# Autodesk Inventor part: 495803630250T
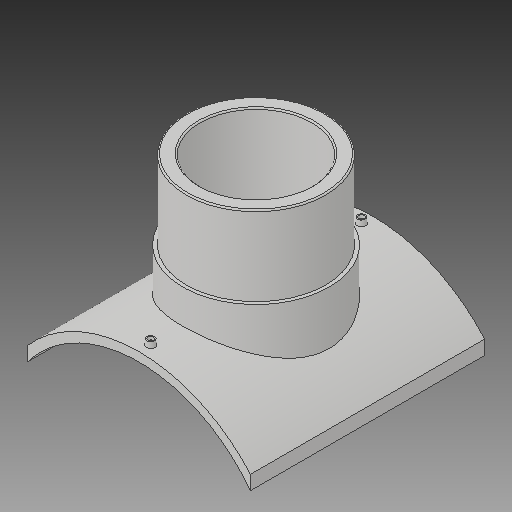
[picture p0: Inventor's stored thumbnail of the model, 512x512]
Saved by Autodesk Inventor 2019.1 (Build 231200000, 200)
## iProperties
Created: 2017-10
Part Number: 495803630250T
Material: Generic
Description: PLASSON BRANCH SADDLE 500x250
Document SubType Name: Modeling
Designer: KIM
Mass: 2754.05 g
Surface Area: 3037.44 cm^2
Volume: 2754.05 cm^3
Density: 1 g/cm^3
Appearance: Default
Author: KIM
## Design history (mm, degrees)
derived "495803.ipt"
feature "Solid1::495803.ipt"
tag "TaggingFeature1"
body "Solid1"
other parameters: "d1" = 16, "d4" = 0, "d12" = 275.6, "d13" = 14, "d14" = 189, "d16" = 5 deg, "d18" = 4, "d19" = 14, "d20" = 0, "d21" = 3, "d22" = 0, "d23" = 469, "d24" = 262.5, "d25" = 16, "d28" = 0, "d29" = 9.6, "d31" = 0, "d32" = 101.5, "d33" = 0, "d34" = 5, "d37" = 142.1, "d38" = 0, "d39" = 2.5, "H_" = 203, "x_" = 16, "D_" = 16
